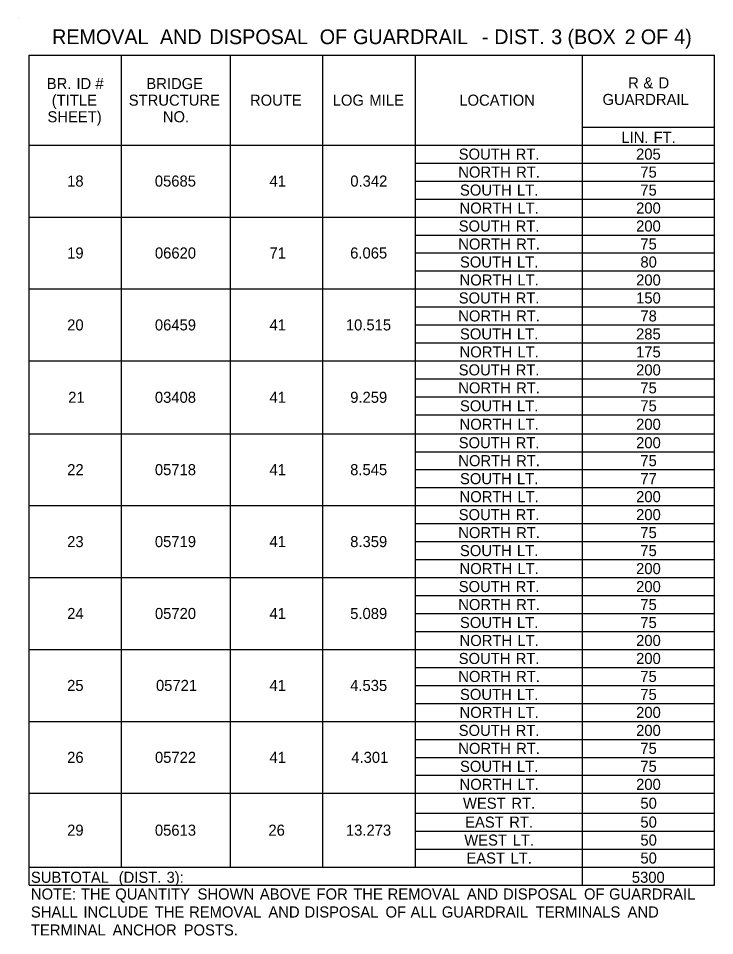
# Model space of a CAD drawing. Extents: x 544250 to 1930787, y -1948365 to 596640.
# Drawn here: x 546506.9 to 546884.7, y -1946734.6 to -1946237.2 of the extents above; entities that cross this region are included whole.
import ezdxf

# ---------------------------------------------------------------- set-up
doc = ezdxf.new("R2010")
doc.units = 0
doc.layers.add('Default', color=7, linetype='Continuous')

msp = doc.modelspace()

# ---------------------------------------------------------------- linework, layer by layer
at = {"layer": 'Default'}
for p, q in [((546506.92, -1946237.21), (546506.92, -1946237.21)), ((546512.77, -1946257.19), (546884.73, -1946257.19)), ((546512.77, -1946707.16), (546512.77, -1946257.19)), ((546512.77, -1946707.16), (546512.77, -1946257.19)), ((546562.98, -1946697.41), (546562.98, -1946257.19)), ((546621.97, -1946697.41), (546621.97, -1946257.19)), ((546672.18, -1946697.41), (546672.18, -1946257.19)), ((546722.4, -1946697.41), (546722.4, -1946257.19)), ((546813.07, -1946707.16), (546813.07, -1946257.19)), ((546884.73, -1946707.16), (546884.73, -1946257.19)), ((546884.73, -1946657.43), (546884.73, -1946257.19)), ((546813.07, -1946296.19), (546884.73, -1946296.19)), ((546512.77, -1946305.94), (546884.73, -1946305.94)), ((546512.77, -1946305.94), (546884.73, -1946305.94)), ((546722.4, -1946315.69), (546884.73, -1946315.69)), ((546722.4, -1946325.44), (546884.73, -1946325.44)), ((546722.4, -1946335.19), (546884.73, -1946335.19)), ((546512.77, -1946344.94), (546884.73, -1946344.94)), ((546722.4, -1946354.69), (546884.73, -1946354.69)), ((546722.4, -1946364.44), (546884.73, -1946364.44)), ((546722.4, -1946374.19), (546884.73, -1946374.19)), ((546512.77, -1946383.94), (546884.73, -1946383.94)), ((546722.4, -1946393.69), (546884.73, -1946393.69)), ((546722.4, -1946403.44), (546884.73, -1946403.44)), ((546722.4, -1946413.19), (546884.73, -1946413.19)), ((546512.77, -1946422.94), (546884.73, -1946422.94)), ((546722.4, -1946432.69), (546884.73, -1946432.69)), ((546722.4, -1946442.44), (546884.73, -1946442.44)), ((546722.4, -1946452.19), (546884.73, -1946452.19)), ((546512.77, -1946462.43), (546884.73, -1946462.43)), ((546722.4, -1946472.18), (546884.73, -1946472.18)), ((546722.4, -1946481.93), (546884.73, -1946481.93)), ((546722.4, -1946491.68), (546884.73, -1946491.68)), ((546512.77, -1946501.43), (546884.73, -1946501.43)), ((546722.4, -1946511.18), (546884.73, -1946511.18)), ((546722.4, -1946520.93), (546884.73, -1946520.93)), ((546722.4, -1946530.68), (546884.73, -1946530.68)), ((546512.77, -1946540.43), (546884.73, -1946540.43)), ((546722.4, -1946550.18), (546884.73, -1946550.18)), ((546722.4, -1946559.93), (546884.73, -1946559.93)), ((546722.4, -1946569.68), (546884.73, -1946569.68)), ((546512.77, -1946579.43), (546884.73, -1946579.43)), ((546722.4, -1946589.18), (546884.73, -1946589.18)), ((546722.4, -1946598.93), (546884.73, -1946598.93)), ((546722.4, -1946608.68), (546884.73, -1946608.68)), ((546512.77, -1946618.43), (546884.73, -1946618.43)), ((546722.4, -1946628.18), (546884.73, -1946628.18)), ((546722.4, -1946637.93), (546884.73, -1946637.93)), ((546722.4, -1946647.68), (546884.73, -1946647.68)), ((546512.77, -1946657.43), (546884.73, -1946657.43)), ((546722.4, -1946668.16), (546884.73, -1946668.16)), ((546884.73, -1946707.16), (546884.73, -1946668.16)), ((546722.4, -1946677.91), (546884.73, -1946677.91)), ((546722.4, -1946687.66), (546884.73, -1946687.66)), ((546512.77, -1946697.41), (546884.73, -1946697.41)), ((546813.07, -1946707.16), (546813.07, -1946697.41)), ((546512.77, -1946707.16), (546884.73, -1946707.16))]:
    msp.add_line(p, q, dxfattribs=at)

# ---------------------------------------------------------------- texts
for s, height, p in [('REMOVAL', 8, (546525.24, -1946251.2)), (' AND', 8, (546580.8, -1946251.2)), (' DISPOSAL', 8, (546607.57, -1946251.2)), (' OF', 8, (546667.48, -1946251.2)), (' GUARDRAIL', 8, (546685.59, -1946251.2)), (' DIST.', 8, (546762.17, -1946251.2)), (' 3', 8, (546793.07, -1946251.2)), (' (BOX', 8, (546801.91, -1946251.2)), (' 2', 8, (546832.95, -1946251.2)), (' OF', 8, (546841.7, -1946251.2)), (' 4)', 8, (546859.81, -1946251.2)), (' -', 8, (546755.43, -1946251.2)), ('BR.', 6, (546522.35, -1946275.57)), (' ID', 6, (546536.22, -1946275.57)), (' #', 6, (546546.51, -1946275.57)), ('BRIDGE', 6, (546576.38, -1946275.57)), ('R', 6, (546837.79, -1946275.19)), (' &', 6, (546843.8, -1946275.19)), (' D', 6, (546852.05, -1946275.19)), ('(TITLE', 6, (546525.05, -1946284.57)), ('STRUCTURE', 6, (546566.83, -1946284.57)), ('ROUTE', 6, (546632.61, -1946284.57)), ('LOG', 6, (546677.49, -1946284.57)), (' MILE', 6, (546695.15, -1946284.57)), ('LOCATION', 6, (546746.18, -1946284.57)), ('GUARDRAIL', 6, (546823.88, -1946284.19)), ('SHEET)', 6, (546522.72, -1946293.57)), ('NO.', 6, (546585.31, -1946293.57)), ('LIN.', 6, (546834.11, -1946304.74)), (' FT.', 6, (546849.37, -1946304.74)), ('SOUTH', 6, (546745.85, -1946313.82)), (' RT.', 6, (546774.52, -1946313.82)), ('205', 6, (546842.08, -1946313.82)), ('NORTH', 6, (546745.62, -1946323.57)), (' RT.', 6, (546774.75, -1946323.57)), ('75', 6, (546844.41, -1946323.57)), ('18', 6, (546533.4, -1946328.44)), ('05685', 6, (546580.99, -1946328.44)), ('41', 6, (546643.19, -1946328.44)), ('0.342', 6, (546687.03, -1946328.44)), ('SOUTH', 6, (546746.55, -1946333.32)), (' LT.', 6, (546775.22, -1946333.32)), ('75', 6, (546844.41, -1946333.32)), ('NORTH', 6, (546746.32, -1946343.07)), (' LT.', 6, (546775.45, -1946343.07)), ('200', 6, (546842.11, -1946343.07)), ('SOUTH', 6, (546745.85, -1946352.82)), (' RT.', 6, (546774.52, -1946352.82)), ('200', 6, (546842.11, -1946352.82)), ('NORTH', 6, (546745.62, -1946362.57)), (' RT.', 6, (546774.75, -1946362.57)), ('75', 6, (546844.41, -1946362.57)), ('19', 6, (546533.4, -1946367.44)), ('06620', 6, (546581.03, -1946367.44)), ('71', 6, (546643.19, -1946367.44)), ('6.065', 6, (546686.97, -1946367.44)), ('SOUTH', 6, (546746.55, -1946372.32)), (' LT.', 6, (546775.22, -1946372.32)), ('80', 6, (546844.44, -1946372.32)), ('NORTH', 6, (546746.32, -1946382.07)), (' LT.', 6, (546775.45, -1946382.07)), ('200', 6, (546842.11, -1946382.07)), ('SOUTH', 6, (546745.85, -1946391.82)), (' RT.', 6, (546774.52, -1946391.82)), ('150', 6, (546842.11, -1946391.82)), ('NORTH', 6, (546745.62, -1946401.57)), (' RT.', 6, (546774.75, -1946401.57)), ('78', 6, (546844.43, -1946401.57)), ('20', 6, (546533.42, -1946406.44)), ('06459', 6, (546581.01, -1946406.44)), ('41', 6, (546643.19, -1946406.44)), ('10.515', 6, (546684.64, -1946406.44)), ('SOUTH', 6, (546746.55, -1946411.32)), (' LT.', 6, (546775.22, -1946411.32)), ('285', 6, (546842.08, -1946411.32)), ('NORTH', 6, (546746.32, -1946421.07)), (' LT.', 6, (546775.45, -1946421.07)), ('175', 6, (546842.08, -1946421.07)), ('SOUTH', 6, (546745.85, -1946430.82)), (' RT.', 6, (546774.52, -1946430.82)), ('200', 6, (546842.11, -1946430.82)), ('NORTH', 6, (546745.62, -1946440.57)), (' RT.', 6, (546774.75, -1946440.57)), ('75', 6, (546844.41, -1946440.57)), ('21', 6, (546533.99, -1946445.69)), ('03408', 6, (546581.01, -1946445.69)), ('41', 6, (546643.19, -1946445.69)), ('9.259', 6, (546686.99, -1946445.69)), ('SOUTH', 6, (546746.55, -1946450.32)), (' LT.', 6, (546775.22, -1946450.32)), ('75', 6, (546844.41, -1946450.32)), ('NORTH', 6, (546746.32, -1946460.31)), (' LT.', 6, (546775.45, -1946460.31)), ('200', 6, (546842.11, -1946460.31)), ('SOUTH', 6, (546745.85, -1946470.31)), (' RT.', 6, (546774.52, -1946470.31)), ('200', 6, (546842.11, -1946470.31)), ('NORTH', 6, (546745.62, -1946480.06)), (' RT.', 6, (546774.75, -1946480.06)), ('75', 6, (546844.41, -1946480.06)), ('22', 6, (546533.44, -1946484.93)), ('05718', 6, (546581.01, -1946484.93)), ('41', 6, (546643.19, -1946484.93)), ('8.545', 6, (546686.97, -1946484.93)), ('SOUTH', 6, (546746.55, -1946489.81)), (' LT.', 6, (546775.22, -1946489.81)), ('77', 6, (546844.43, -1946489.81)), ('NORTH', 6, (546746.32, -1946499.56)), (' LT.', 6, (546775.45, -1946499.56)), ('200', 6, (546842.11, -1946499.56)), ('SOUTH', 6, (546745.85, -1946509.31)), (' RT.', 6, (546774.52, -1946509.31)), ('200', 6, (546842.11, -1946509.31)), ('NORTH', 6, (546745.62, -1946519.06)), (' RT.', 6, (546774.75, -1946519.06)), ('75', 6, (546844.41, -1946519.06)), ('23', 6, (546533.41, -1946523.93)), ('05719', 6, (546581.01, -1946523.93)), ('41', 6, (546643.19, -1946523.93)), ('8.359', 6, (546686.99, -1946523.93)), ('SOUTH', 6, (546746.55, -1946528.81)), (' LT.', 6, (546775.22, -1946528.81)), ('75', 6, (546844.41, -1946528.81)), ('NORTH', 6, (546746.32, -1946538.56)), (' LT.', 6, (546775.45, -1946538.56)), ('200', 6, (546842.11, -1946538.56)), ('SOUTH', 6, (546745.85, -1946548.31)), (' RT.', 6, (546774.52, -1946548.31)), ('200', 6, (546842.11, -1946548.31)), ('NORTH', 6, (546745.62, -1946558.06)), (' RT.', 6, (546774.75, -1946558.06)), ('75', 6, (546844.41, -1946558.06)), ('24', 6, (546533.42, -1946562.93)), ('05720', 6, (546581.03, -1946562.93)), ('41', 6, (546643.19, -1946562.93)), ('5.089', 6, (546686.99, -1946562.93)), ('SOUTH', 6, (546746.55, -1946567.81)), (' LT.', 6, (546775.22, -1946567.81)), ('75', 6, (546844.41, -1946567.81)), ('NORTH', 6, (546746.32, -1946577.56)), (' LT.', 6, (546775.45, -1946577.56)), ('200', 6, (546842.11, -1946577.56)), ('SOUTH', 6, (546745.85, -1946587.31)), (' RT.', 6, (546774.52, -1946587.31)), ('200', 6, (546842.11, -1946587.31)), ('NORTH', 6, (546745.62, -1946597.06)), (' RT.', 6, (546774.75, -1946597.06)), ('75', 6, (546844.41, -1946597.06)), ('25', 6, (546533.38, -1946601.93)), ('05721', 6, (546581.6, -1946601.93)), ('41', 6, (546643.19, -1946601.93)), ('4.535', 6, (546686.97, -1946601.93)), ('SOUTH', 6, (546746.55, -1946606.81)), (' LT.', 6, (546775.22, -1946606.81)), ('75', 6, (546844.41, -1946606.81)), ('NORTH', 6, (546746.32, -1946616.56)), (' LT.', 6, (546775.45, -1946616.56)), ('200', 6, (546842.11, -1946616.56)), ('SOUTH', 6, (546745.85, -1946626.31)), (' RT.', 6, (546774.52, -1946626.31)), ('200', 6, (546842.11, -1946626.31)), ('NORTH', 6, (546745.62, -1946636.06)), (' RT.', 6, (546774.75, -1946636.06)), ('75', 6, (546844.41, -1946636.06)), ('26', 6, (546533.41, -1946640.93)), ('05722', 6, (546581.05, -1946640.93)), ('41', 6, (546643.19, -1946640.93)), ('4.301', 6, (546687.58, -1946640.93)), ('SOUTH', 6, (546746.55, -1946645.81)), (' LT.', 6, (546775.22, -1946645.81)), ('75', 6, (546844.41, -1946645.81)), ('NORTH', 6, (546746.32, -1946655.56)), ('200', 6, (546842.11, -1946655.56)), (' LT.', 6, (546775.45, -1946655.56)), ('WEST', 6, (546748.16, -1946665.79)), (' RT.', 6, (546772.21, -1946665.79)), ('50', 6, (546844.44, -1946665.79)), ('29', 6, (546533.4, -1946680.42)), ('05613', 6, (546581.02, -1946680.42)), ('26', 6, (546642.61, -1946680.42)), ('13.273', 6, (546684.67, -1946680.42)), ('EAST', 6, (546749.32, -1946676.03)), (' RT.', 6, (546771.05, -1946676.03)), ('50', 6, (546844.44, -1946676.03)), ('WEST', 6, (546748.86, -1946685.78)), (' LT.', 6, (546772.91, -1946685.78)), ('50', 6, (546844.44, -1946685.78)), ('EAST', 6, (546750.02, -1946695.53)), (' LT.', 6, (546771.75, -1946695.53)), ('50', 6, (546844.44, -1946695.53)), ('SUBTOTAL', 6, (546513.75, -1946705.96)), (' (DIST.', 6, (546559.14, -1946705.96)), (' 3):', 6, (546585.11, -1946705.96)), ('5300', 6, (546839.79, -1946705.96)), ('NOTE:', 6, (546513.75, -1946715.03)), (' THE', 6, (546538.63, -1946715.03)), (' QUANTITY', 6, (546557.28, -1946715.03)), (' SHOWN', 6, (546601.94, -1946715.03)), (' ABOVE', 6, (546635.71, -1946715.03)), (' FOR', 6, (546666.49, -1946715.03)), (' THE', 6, (546686.4, -1946715.03)), (' REMOVAL', 6, (546705.05, -1946715.03)), (' AND', 6, (546748.08, -1946715.03)), (' DISPOSAL', 6, (546767.66, -1946715.03)), (' OF', 6, (546811.62, -1946715.03)), (' GUARDRAIL', 6, (546825.21, -1946715.03)), ('SHALL', 6, (546513.75, -1946724.78)), (' INCLUDE', 6, (546540.01, -1946724.78)), (' THE', 6, (546578.69, -1946724.78)), (' REMOVAL', 6, (546597.34, -1946724.78)), (' AND', 6, (546640.37, -1946724.78)), (' DISPOSAL', 6, (546659.95, -1946724.78)), (' OF', 6, (546703.92, -1946724.78)), (' ALL', 6, (546717.5, -1946724.78)), (' GUARDRAIL', 6, (546734.45, -1946724.78)), (' TERMINALS', 6, (546785.39, -1946724.78)), (' AND', 6, (546835.26, -1946724.78)), ('TERMINAL', 6, (546513.75, -1946734.53)), (' ANCHOR', 6, (546555.84, -1946734.53)), (' POSTS.', 6, (546594.39, -1946734.53))]:
    msp.add_text(s, height=height, dxfattribs=at).set_placement(p)

doc.saveas('drawing.dxf')
